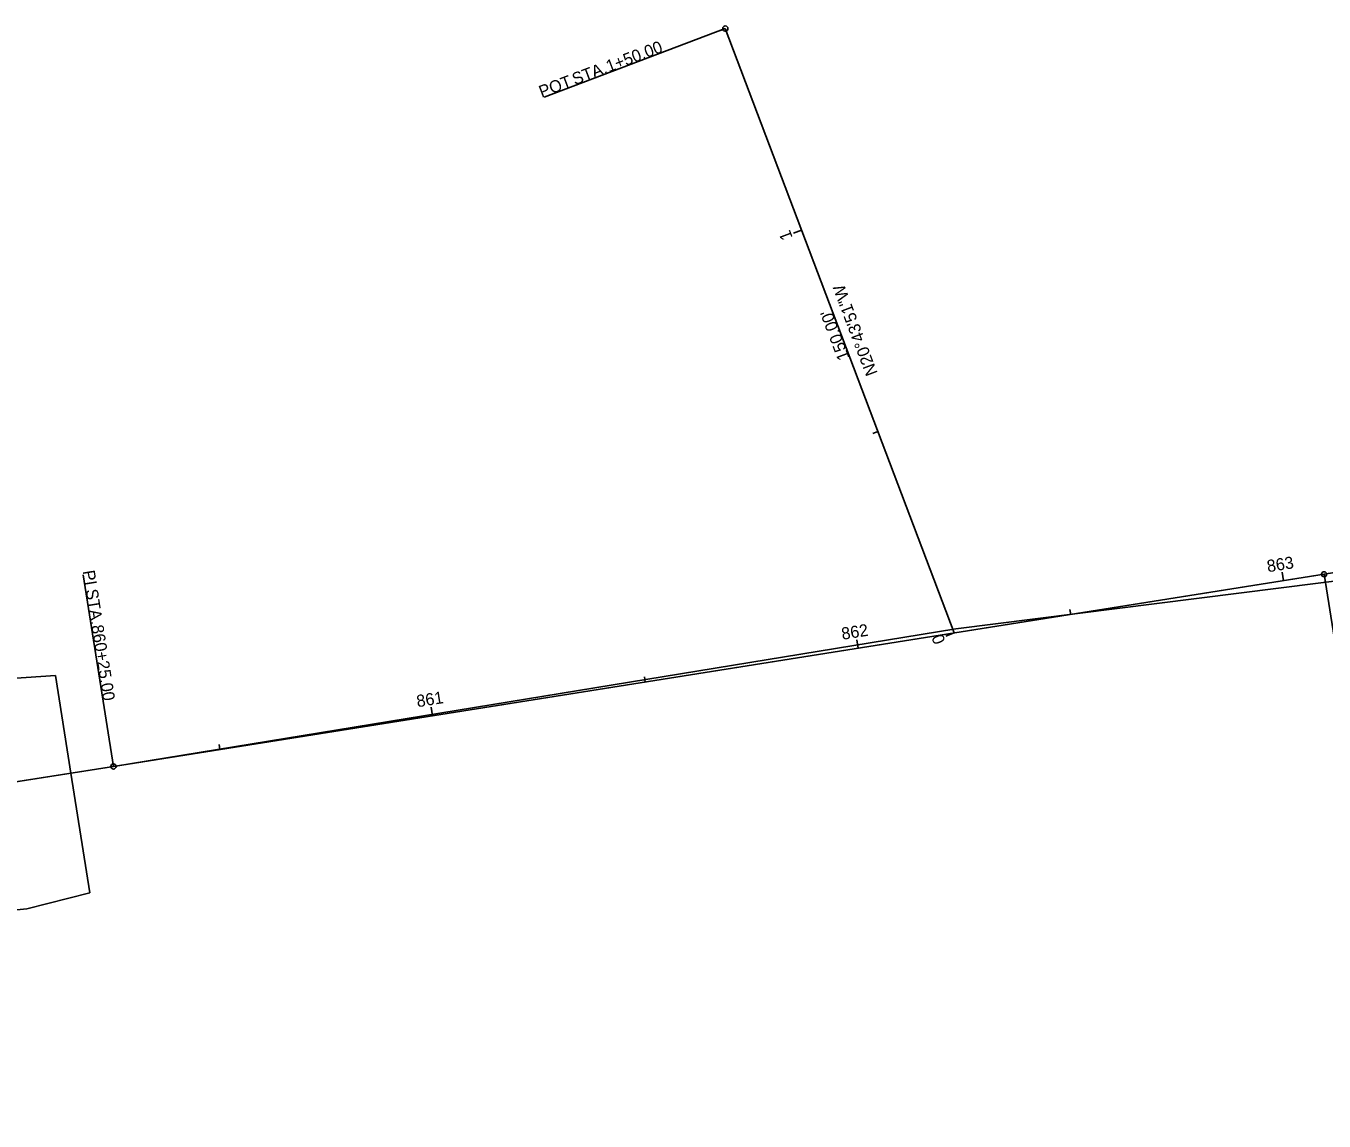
# Model space of a CAD drawing. Extents: x 115987 to 120394, y 324408 to 325987.
# Drawn here: x 117550.6 to 117851.9, y 325416.9 to 325671.1 of the extents above; entities that cross this region are included whole.
import ezdxf

# ---------------------------------------------------------------- set-up
doc = ezdxf.new("R2010")
doc.units = 0
for name, color, linetype in [('_CIVIL_CONSTRUCTION', 7, 'Continuous'), ('DT_X_Break_Line', 7, 'Continuous'), ('DT_X_Contour_Major', 7, 'Continuous'), ('DT_X_Island', 7, 'Continuous'), ('DT_X_Terrain_Boundary', 7, 'Continuous'), ('DT_X_Void', 7, 'Continuous'), ('UT_X_Gas_Cells', 7, 'Continuous')]:
    doc.layers.add(name, color=color, linetype=linetype)

msp = doc.modelspace()

# ---------------------------------------------------------------- linework, layer by layer
at = {"layer": '_CIVIL_CONSTRUCTION'}
msp.add_lwpolyline([(117546.25, 325495.29), (117570.94, 325499.21), (117766.5, 325531.11), (117916.3, 325550), (117982.12, 325552.99), (118061.23, 325550.63), (118140.16, 325542.3), (118267.24, 325523.46), (118330.42, 325512.77)], dxfattribs=at)
at = {"layer": 'DT_X_Contour_Major'}
for p, q in [((117766.06, 325530.18), (117712.97, 325670.46)), ((117570.94, 325499.21), (118010.69, 325569)), ((117570.94, 325499.21), (117851.95, 325543.81)), ((117570.94, 325499.21), (117851.95, 325543.81)), ((117052.43, 325416.91), (117570.94, 325499.21))]:
    msp.add_line(p, q, dxfattribs=at)
at = {"layer": 'DT_X_Terrain_Boundary'}
for p, q in [((117712.97, 325670.46), (117711.84, 325670.04)), ((117730.66, 325623.7), (117728.79, 325622.99)), ((117748.36, 325576.94), (117747.24, 325576.51)), ((117842.54, 325542.31), (117842.22, 325544.29)), ((117793.16, 325534.48), (117792.97, 325535.66)), ((117743.77, 325526.64), (117743.46, 325528.61)), ((117766.06, 325530.18), (117764.19, 325529.47)), ((117694.39, 325518.8), (117694.2, 325519.99)), ((117645.01, 325510.96), (117644.7, 325512.94)), ((117595.63, 325503.13), (117595.44, 325504.31))]:
    msp.add_line(p, q, dxfattribs=at)
at = {"layer": 'DT_X_Void'}
for p, q in [((117712.97, 325670.46), (117670.88, 325654.53)), ((117570.94, 325499.21), (117563.88, 325543.65)), ((117851.95, 325543.81), (117859, 325499.36))]:
    msp.add_line(p, q, dxfattribs=at)
for centre in [(117712.97, 325670.46), (117851.95, 325543.81), (117570.94, 325499.21)]:
    msp.add_circle(centre, 0.6, dxfattribs=at)
at = {"layer": 'UT_X_Gas_Cells'}
for p, q in [((117542.43, 325519.32), (117557.46, 325520.32)), ((117557.46, 325520.32), (117561.06, 325497.64)), ((117561.06, 325497.64), (117565.47, 325469.89)), ((117550.86, 325466.19), (117565.47, 325469.89)), ((117525.95, 325463.67), (117550.86, 325466.19))]:
    msp.add_line(p, q, dxfattribs=at)

# ---------------------------------------------------------------- texts
at = {"layer": 'DT_X_Break_Line'}
msp.add_text('N20°43\'51"W', height=2.8, rotation=110.7309, dxfattribs=at).set_placement((117748.36, 325590.5))
at = {"layer": 'DT_X_Island'}
msp.add_text("150.00'", height=2.8, rotation=110.7309, dxfattribs=at).set_placement((117741.84, 325594.06))
at = {"layer": 'DT_X_Terrain_Boundary'}
for s, rotation, p in [('1', 110.7309, (117728.65, 325621.96)), ('863', 9.0184, (117838.91, 325544.27)), ('862', 9.0184, (117740.14, 325528.59)), ('0', 110.7309, (117764.12, 325528.25)), ('861', 9.0184, (117641.51, 325512.94))]:
    msp.add_text(s, height=2.8, rotation=rotation, dxfattribs=at).set_placement(p)
at = {"layer": 'DT_X_Void'}
for s, rotation, p in [('1+50.00', 20.7309, (117685.91, 325660.27)), (' STA. ', 20.7309, (117677.07, 325656.92)), ('POT', 20.7309, (117670.34, 325654.37)), ('PI', 279.0184, (117563.79, 325544.54)), (' STA. ', 279.0184, (117564.32, 325541.19)), ('860+25.00', 279.0184, (117565.8, 325531.86))]:
    msp.add_text(s, height=2.8, rotation=rotation, dxfattribs=at).set_placement(p)

doc.saveas('drawing.dxf')
